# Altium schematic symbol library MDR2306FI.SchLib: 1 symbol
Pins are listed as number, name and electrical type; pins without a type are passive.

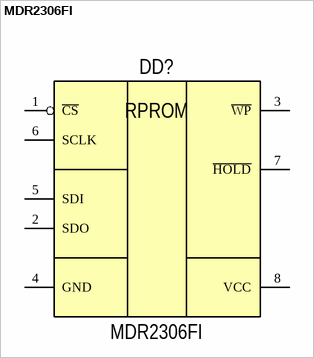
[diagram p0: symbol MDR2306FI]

## MDR2306FI
designator DD?
Микросхема ЭСППЗУ Flash-типа с последовательным интерфейсом SPI
pins: 1 ~{CS}, 2 SDO, 3 ~{WP}, 4 GND, 5 SDI, 6 SCLK, 7 ~{HOLD}, 8 VCC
